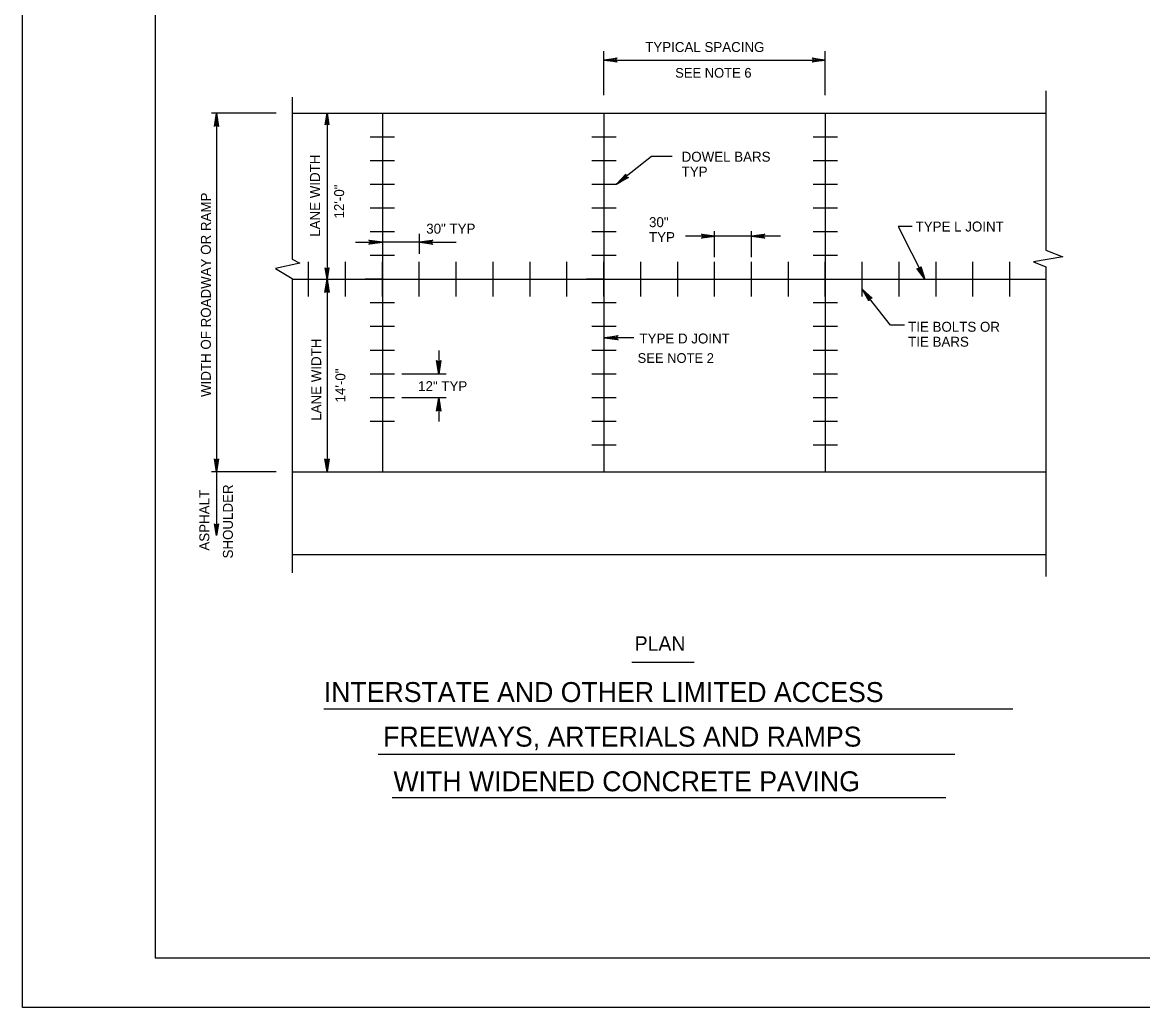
# Model space of a CAD drawing. Extents: x 637877 to 639321, y 297902 to 299090.
# Drawn here: x 638415.5 to 638752.7, y 297901.6 to 298198 of the extents above; entities that cross this region are included whole.
import ezdxf

# ---------------------------------------------------------------- set-up
doc = ezdxf.new("R2010")
doc.units = 0
for name, color, linetype in [('1', 7, 'Continuous'), ('2', 7, 'Continuous'), ('3', 7, 'Continuous'), ('PLT-BNDY', 7, 'Continuous')]:
    doc.layers.add(name, color=color, linetype=linetype)

msp = doc.modelspace()

# ---------------------------------------------------------------- linework, layer by layer
at = {"layer": '1'}
for points in [[(639241.51, 297916.57), (639241.51, 298480.57), (638455.51, 298480.57), (638455.51, 297916.57), (639241.51, 297916.57), (639241.51, 297942.93), (639041.51, 297942.93), (639041.51, 298007.61), (639241.51, 298007.61), (639241.51, 298036.57), (639041.51, 298036.57), (639041.51, 297916.57), (639120.32, 297916.57), (639120.32, 297942.93), (639120.32, 297916.57), (639197.32, 297916.57), (639197.32, 297942.93), (639197.32, 297930.61), (639241.51, 297930.61)], [(638506.81, 298167.42), (638507.05, 298167.54), (638507.23, 298170.73), (638506.81, 298167.42), (638506.67, 298167.25), (638507.23, 298170.73), (638507.38, 298167.55), (638507.62, 298167.43), (638507.23, 298170.73), (638507.78, 298167.25), (638507.62, 298167.43)], [(638597.71, 298151.38), (638597.42, 298151.51), (638594.4, 298149.38), (638597.71, 298151.38), (638597.97, 298151.37), (638594.4, 298149.38), (638597.18, 298151.82), (638597.12, 298152.12), (638594.4, 298149.38), (638597.16, 298152.39), (638597.12, 298152.12)], [(638520.05, 298132.38), (638520.19, 298132.1), (638523.89, 298131.9), (638520.05, 298132.38), (638519.85, 298132.55), (638523.89, 298131.9), (638520.19, 298131.72), (638520.06, 298131.44), (638523.89, 298131.9), (638519.85, 298131.26), (638520.06, 298131.44)], [(638538.85, 298131.42), (638538.7, 298131.69), (638535, 298131.9), (638538.85, 298131.42), (638539.04, 298131.25), (638535, 298131.9), (638538.7, 298132.08), (638538.84, 298132.36), (638535, 298131.9), (638539.04, 298132.54), (638538.84, 298132.36)], [(638507.64, 298124.04), (638507.4, 298123.92), (638507.23, 298120.73), (638507.64, 298124.04), (638507.79, 298124.21), (638507.23, 298120.73), (638507.07, 298123.92), (638506.83, 298124.03), (638507.23, 298120.73), (638506.67, 298124.21), (638506.83, 298124.03)], [(638594.64, 298102.66), (638594.49, 298102.94), (638590.79, 298103.14), (638594.64, 298102.66), (638594.83, 298102.49), (638590.79, 298103.14), (638594.49, 298103.33), (638594.62, 298103.6), (638590.79, 298103.14), (638594.83, 298103.78), (638594.62, 298103.6)], [(638541.31, 298096.07), (638541.03, 298095.93), (638540.83, 298092.23), (638541.31, 298096.07), (638541.48, 298096.27), (638540.83, 298092.23), (638540.65, 298095.93), (638540.37, 298096.06), (638540.83, 298092.23), (638540.19, 298096.27), (638540.37, 298096.06)], [(638540.35, 298081.26), (638540.63, 298081.4), (638540.83, 298085.1), (638540.35, 298081.26), (638540.18, 298081.06), (638540.83, 298085.1), (638541.01, 298081.4), (638541.29, 298081.27), (638540.83, 298085.1), (638541.47, 298081.06), (638541.29, 298081.27)], [(638474.35, 298046.97), (638474.11, 298046.84), (638473.94, 298043.66), (638474.35, 298046.97), (638474.5, 298047.14), (638473.94, 298043.66), (638473.78, 298046.84), (638473.54, 298046.96), (638473.94, 298043.66), (638473.38, 298047.14), (638473.54, 298046.96)]]:
    msp.add_lwpolyline(points, dxfattribs=at)
at = {"layer": '2'}
for p, q in [((638590.56, 298176.13), (638590.56, 298189.34)), ((638657.22, 298176.13), (638657.22, 298189.34)), ((638590.56, 298186.72), (638657.22, 298186.72)), ((638496.73, 298175.57), (638496.73, 298126.82)), ((638723.62, 298177.4), (638723.62, 298129.5)), ((638491.86, 298170.73), (638472.48, 298170.73)), ((638473.94, 298170.73), (638473.94, 298043.66)), ((638496.73, 298170.73), (638723.62, 298170.73)), ((638507.23, 298170.73), (638507.23, 298120.73)), ((638523.89, 298170.73), (638523.89, 298062.77)), ((638590.56, 298170.73), (638590.56, 298062.77)), ((638657.22, 298170.73), (638657.22, 298062.77)), ((638604.89, 298157.68), (638594.4, 298149.38)), ((638611.08, 298157.68), (638604.89, 298157.68)), ((638623.89, 298127.4), (638623.89, 298135.17)), ((638635, 298127.4), (638635, 298135.17)), ((638515.8, 298131.9), (638523.89, 298131.9)), ((638535, 298131.9), (638523.89, 298131.9)), ((638535, 298134.39), (638535, 298128.4)), ((638535, 298131.9), (638546.11, 298131.9)), ((638635, 298133.72), (638615.14, 298133.72)), ((638643.75, 298133.72), (638635, 298133.72)), ((638723.62, 298124.47), (638723.62, 298031.33)), ((638723.24, 298122.8), (638723.24, 298122.8)), ((638723.24, 298122.8), (638723.24, 298122.8)), ((638723.24, 298122.8), (638723.24, 298122.8)), ((638723.24, 298122.8), (638723.24, 298122.8)), ((638723.24, 298122.8), (638723.24, 298122.8)), ((638723.24, 298122.8), (638723.24, 298122.8)), ((638723.24, 298122.8), (638723.24, 298122.8)), ((638723.24, 298122.8), (638723.24, 298122.8)), ((638723.24, 298122.8), (638723.24, 298122.8)), ((638723.24, 298122.8), (638723.24, 298122.8)), ((638723.24, 298122.8), (638723.24, 298122.8)), ((638496.73, 298121.01), (638496.73, 298032.43)), ((638496.73, 298120.73), (638723.62, 298120.73)), ((638500.67, 298120.73), (638500.9, 298120.73)), ((638501.67, 298120.73), (638501.67, 298120.73)), ((638507.23, 298120.73), (638507.23, 298062.77)), ((638507.23, 298120.73), (638507.23, 298120.73)), ((638507.93, 298120.73), (638507.93, 298120.73)), ((638518.34, 298120.73), (638518.34, 298120.73)), ((638523.89, 298120.73), (638523.89, 298120.73)), ((638529.45, 298120.73), (638529.45, 298120.73)), ((638529.45, 298120.73), (638529.45, 298120.73)), ((638529.45, 298120.73), (638529.45, 298120.73)), ((638529.45, 298120.73), (638529.45, 298120.73)), ((638529.45, 298120.73), (638529.45, 298120.73)), ((638535, 298120.73), (638535, 298120.73)), ((638540.56, 298120.73), (638540.56, 298120.73)), ((638546.11, 298120.73), (638546.11, 298120.73)), ((638551.67, 298120.73), (638551.67, 298120.73)), ((638557.22, 298120.73), (638557.22, 298120.73)), ((638562.78, 298120.73), (638562.78, 298120.73)), ((638568.34, 298120.73), (638568.34, 298120.73)), ((638573.89, 298120.73), (638573.89, 298120.73)), ((638579.45, 298120.73), (638579.45, 298120.73)), ((638585, 298120.73), (638585, 298120.73)), ((638590.56, 298120.73), (638590.56, 298120.73)), ((638596.11, 298120.73), (638596.11, 298120.73)), ((638596.11, 298120.73), (638596.11, 298120.73)), ((638596.11, 298120.73), (638596.11, 298120.73)), ((638596.11, 298120.73), (638596.11, 298120.73)), ((638596.11, 298120.73), (638596.11, 298120.73)), ((638601.67, 298120.73), (638601.67, 298120.73)), ((638607.22, 298120.73), (638607.22, 298120.73)), ((638612.78, 298120.73), (638612.78, 298120.73)), ((638618.33, 298120.73), (638618.33, 298120.73)), ((638623.89, 298120.73), (638623.89, 298120.73)), ((638629.44, 298120.73), (638629.44, 298120.73)), ((638635, 298120.73), (638635, 298120.73)), ((638640.55, 298120.73), (638640.55, 298120.73)), ((638646.11, 298120.73), (638646.11, 298120.73)), ((638657.22, 298120.73), (638657.22, 298120.73)), ((638662.78, 298120.73), (638662.78, 298120.73)), ((638662.78, 298120.73), (638662.78, 298120.73)), ((638662.78, 298120.73), (638662.78, 298120.73)), ((638662.78, 298120.73), (638662.78, 298120.73)), ((638662.78, 298120.73), (638662.78, 298120.73)), ((638668.33, 298120.73), (638668.33, 298120.73)), ((638673.89, 298120.73), (638673.89, 298120.73)), ((638679.44, 298120.73), (638679.44, 298120.73)), ((638685, 298120.73), (638685, 298120.73)), ((638690.55, 298120.73), (638690.55, 298120.73)), ((638696.11, 298120.73), (638696.11, 298120.73)), ((638701.66, 298120.73), (638701.66, 298120.73)), ((638707.22, 298120.73), (638707.22, 298120.73)), ((638712.77, 298120.73), (638712.77, 298120.73)), ((638599.54, 298103.14), (638590.79, 298103.14)), ((638540.83, 298099.35), (638540.83, 298092.23)), ((638543.04, 298092.23), (638529.74, 298092.23)), ((638543.04, 298085.1), (638529.74, 298085.1)), ((638540.83, 298085.1), (638540.83, 298077.98)), ((638491.86, 298062.77), (638472.48, 298062.77)), ((638496.73, 298062.77), (638723.62, 298062.77)), ((638496.73, 298037.95), (638723.62, 298037.95))]:
    msp.add_line(p, q, dxfattribs=at)
for points in [[(638594.34, 298186.25), (638594.2, 298186.52), (638590.56, 298186.72), (638594.34, 298186.25), (638594.54, 298186.08), (638590.56, 298186.72), (638594.2, 298186.9), (638594.33, 298187.17), (638590.56, 298186.72), (638594.54, 298187.36), (638594.33, 298187.17)], [(638653.44, 298187.2), (638653.58, 298186.92), (638657.22, 298186.72), (638653.44, 298187.2), (638653.24, 298187.36), (638657.22, 298186.72), (638653.58, 298186.54), (638653.45, 298186.27), (638657.22, 298186.72), (638653.24, 298186.09), (638653.45, 298186.27)], [(638473.46, 298166.95), (638473.74, 298167.09), (638473.94, 298170.73), (638473.46, 298166.95), (638473.3, 298166.75), (638473.94, 298170.73), (638474.12, 298167.09), (638474.39, 298166.96), (638473.94, 298170.73), (638474.57, 298166.75), (638474.39, 298166.96)], [(638527.55, 298163.49), (638520.23, 298163.49)], [(638594.22, 298163.49), (638586.9, 298163.49)], [(638660.88, 298163.49), (638653.56, 298163.49)], [(638527.55, 298156.37), (638523.89, 298156.37), (638520.23, 298156.37)], [(638594.22, 298156.37), (638590.56, 298156.37), (638586.9, 298156.37)], [(638660.88, 298156.37), (638657.22, 298156.37), (638653.56, 298156.37)], [(638527.55, 298149.24), (638520.23, 298149.24)], [(638594.22, 298149.24), (638586.9, 298149.24)], [(638660.88, 298149.24), (638653.56, 298149.24)], [(638527.55, 298142.11), (638523.89, 298142.11), (638520.23, 298142.11)], [(638594.22, 298142.11), (638590.56, 298142.11), (638586.9, 298142.11)], [(638660.88, 298142.11), (638657.22, 298142.11), (638653.56, 298142.11)], [(638527.55, 298134.99), (638520.23, 298134.99)], [(638594.22, 298134.99), (638586.9, 298134.99)], [(638660.88, 298134.99), (638653.56, 298134.99)], [(638683.35, 298136.61), (638679.18, 298136.61), (638687.16, 298120.73)], [(638620.11, 298134.19), (638620.25, 298133.92), (638623.89, 298133.72), (638620.11, 298134.19), (638619.91, 298134.36), (638623.89, 298133.72), (638620.25, 298133.54), (638620.12, 298133.26), (638623.89, 298133.72), (638619.91, 298133.08), (638620.12, 298133.26)], [(638638.78, 298133.24), (638638.64, 298133.51), (638635, 298133.72), (638638.78, 298133.24), (638638.98, 298133.08), (638635, 298133.72), (638638.64, 298133.9), (638638.77, 298134.17), (638635, 298133.72), (638638.98, 298134.35), (638638.77, 298134.17)], [(638527.55, 298127.86), (638523.89, 298127.86), (638520.23, 298127.86)], [(638594.22, 298127.86), (638590.56, 298127.86), (638586.9, 298127.86)], [(638660.88, 298127.86), (638657.22, 298127.86), (638653.56, 298127.86)], [(638723.62, 298129.5), (638728.73, 298127.46), (638719.93, 298126.03), (638723.62, 298124.47)], [(638496.73, 298126.82), (638499.04, 298125.57), (638491.73, 298123.96), (638496.73, 298121.01)], [(638501.67, 298115.53), (638501.67, 298120.73), (638501.67, 298125.94)], [(638512.78, 298115.53), (638512.78, 298120.73), (638512.78, 298125.94)], [(638523.89, 298115.53), (638523.89, 298120.73), (638523.89, 298125.94)], [(638535, 298115.53), (638535, 298120.73), (638535, 298125.94)], [(638546.11, 298115.53), (638546.11, 298120.73), (638546.11, 298125.94)], [(638557.22, 298115.53), (638557.22, 298120.73), (638557.22, 298125.94)], [(638568.34, 298115.53), (638568.34, 298120.73), (638568.34, 298125.94)], [(638579.45, 298115.53), (638579.45, 298120.73), (638579.45, 298125.94)], [(638590.56, 298115.53), (638590.56, 298120.73), (638590.56, 298125.94)], [(638601.67, 298115.53), (638601.67, 298120.73), (638601.67, 298125.94)], [(638612.78, 298115.53), (638612.78, 298120.73), (638612.78, 298125.94)], [(638623.89, 298115.53), (638623.89, 298120.73), (638623.89, 298125.94)], [(638635, 298115.53), (638635, 298120.73), (638635, 298125.94)], [(638646.11, 298115.53), (638646.11, 298120.73), (638646.11, 298125.94)], [(638657.22, 298115.53), (638657.22, 298120.73), (638657.22, 298125.94)], [(638668.33, 298115.53), (638668.33, 298120.73), (638668.33, 298125.94)], [(638679.44, 298115.53), (638679.44, 298120.73), (638679.44, 298125.94)], [(638685.88, 298124.33), (638685.7, 298124.08), (638687.16, 298120.73), (638685.88, 298124.33), (638685.95, 298124.58), (638687.16, 298120.73), (638685.36, 298123.91), (638685.06, 298123.9), (638687.16, 298120.73), (638684.81, 298124), (638685.06, 298123.9)], [(638690.55, 298115.53), (638690.55, 298120.73), (638690.55, 298125.94)], [(638701.66, 298115.53), (638701.66, 298120.73), (638701.66, 298125.94)], [(638712.77, 298115.53), (638712.77, 298120.73), (638712.77, 298125.94)], [(638506.75, 298116.95), (638507.03, 298117.09), (638507.23, 298120.73), (638506.75, 298116.95), (638506.59, 298116.76), (638507.23, 298120.73), (638507.41, 298117.1), (638507.68, 298116.96), (638507.23, 298120.73), (638507.86, 298116.76), (638507.68, 298116.96)], [(638523.89, 298120.73), (638518.68, 298120.73)], [(638590.56, 298120.73), (638585.35, 298120.73)], [(638681.02, 298106.96), (638676.85, 298106.96), (638668.33, 298117.76)], [(638670.3, 298114.5), (638670.43, 298114.78), (638668.33, 298117.76), (638670.3, 298114.5), (638670.29, 298114.24), (638668.33, 298117.76), (638670.73, 298115.02), (638671.02, 298115.08), (638668.33, 298117.76), (638671.29, 298115.03), (638671.02, 298115.08)], [(638527.55, 298113.61), (638523.89, 298113.61), (638520.23, 298113.61)], [(638594.22, 298113.61), (638590.56, 298113.61), (638586.9, 298113.61)], [(638660.88, 298113.61), (638657.22, 298113.61), (638653.56, 298113.61)], [(638527.55, 298106.48), (638520.23, 298106.48)], [(638594.22, 298106.48), (638586.9, 298106.48)], [(638660.88, 298106.48), (638653.56, 298106.48)], [(638527.55, 298099.35), (638523.89, 298099.35), (638520.23, 298099.35)], [(638594.22, 298099.35), (638590.56, 298099.35), (638586.9, 298099.35)], [(638660.88, 298099.35), (638657.22, 298099.35), (638653.56, 298099.35)], [(638527.55, 298092.23), (638520.23, 298092.23)], [(638594.22, 298092.23), (638586.9, 298092.23)], [(638660.88, 298092.23), (638653.56, 298092.23)], [(638527.55, 298085.1), (638523.89, 298085.1), (638520.23, 298085.1)], [(638594.22, 298085.1), (638590.56, 298085.1), (638586.9, 298085.1)], [(638660.88, 298085.1), (638657.22, 298085.1), (638653.56, 298085.1)], [(638527.55, 298077.98), (638520.23, 298077.98)], [(638594.22, 298077.98), (638586.9, 298077.98)], [(638660.88, 298077.98), (638653.56, 298077.98)], [(638594.22, 298070.85), (638590.56, 298070.85), (638586.9, 298070.85)], [(638660.88, 298070.85), (638657.22, 298070.85), (638653.56, 298070.85)], [(638474.41, 298066.55), (638474.14, 298066.41), (638473.94, 298062.77), (638474.41, 298066.55), (638474.58, 298066.75), (638473.94, 298062.77), (638473.76, 298066.41), (638473.49, 298066.54), (638473.94, 298062.77), (638473.3, 298066.75), (638473.49, 298066.54)], [(638507.7, 298066.55), (638507.43, 298066.41), (638507.23, 298062.77), (638507.7, 298066.55), (638507.87, 298066.75), (638507.23, 298062.77), (638507.05, 298066.41), (638506.78, 298066.54), (638507.23, 298062.77), (638506.59, 298066.75), (638506.78, 298066.54)]]:
    msp.add_lwpolyline(points, dxfattribs=at)
at = {"layer": '3'}
for p, q in [((638599.01, 298005.54), (638617.74, 298005.54)), ((638506.27, 297991.43), (638713.64, 297991.43)), ((638522.66, 297977.87), (638696.26, 297977.87)), ((638526.8, 297964.79), (638693.49, 297964.79))]:
    msp.add_line(p, q, dxfattribs=at)
at = {"layer": 'PLT-BNDY'}
msp.add_lwpolyline([(638415.51, 298495.57), (639256.51, 298495.57), (639256.51, 297901.57), (638415.51, 297901.57)], close=True, dxfattribs=at)

# ---------------------------------------------------------------- texts
at = {"layer": '2'}
for s, p in [('DOWEL BARS', (638613.98, 298156.12)), ('TYP', (638613.98, 298151.62)), ('30"', (638604.15, 298136.43)), ('TYP', (638604.15, 298131.93))]:
    msp.add_text(s, height=3, dxfattribs=at).set_placement(p)
at = {"layer": '3'}
for s, height, p in [('TYPICAL SPACING', 2.9997, (638603.01, 298189.13)), ('SEE NOTE 6', 2.917, (638612.04, 298181.41)), ('TYPE L JOINT', 2.9997, (638684.42, 298135.11)), ('30" TYP', 3, (638537.09, 298134.47)), ('TIE BOLTS OR', 2.9997, (638682.16, 298104.95)), ('TYPE D JOINT', 2.9997, (638601.28, 298101.42)), ('TIE BARS', 3, (638682.16, 298100.45)), ('SEE NOTE 2', 2.917, (638600.72, 298095.58)), ('12" TYP', 3, (638534.64, 298087.07)), ('PLAN', 4.375, (638599.82, 298008.94)), ('INTERSTATE AND OTHER LIMITED ACCESS', 6, (638506.25, 297993.52)), ('FREEWAYS, ARTERIALS AND RAMPS', 6, (638524.11, 297980.1)), ('WITH WIDENED CONCRETE PAVING', 6, (638527.23, 297966.67))]:
    msp.add_text(s, height=height, dxfattribs=at).set_placement(p)
for s, height, p in [('LANE WIDTH', 3, (638505.09, 298133.53)), ('12\'-0"', 3, (638512.37, 298139.03)), ('WIDTH OF ROADWAY OR RAMP', 2.9997, (638472.24, 298085.32)), ('LANE WIDTH', 3, (638505.47, 298078.16)), ('14\'-0"', 3, (638512.75, 298083.67)), ('ASPHALT', 3, (638471.79, 298039.09)), ('SHOULDER', 3, (638478.88, 298036.73))]:
    msp.add_text(s, height=height, rotation=90, dxfattribs=at).set_placement(p)

doc.saveas('drawing.dxf')
